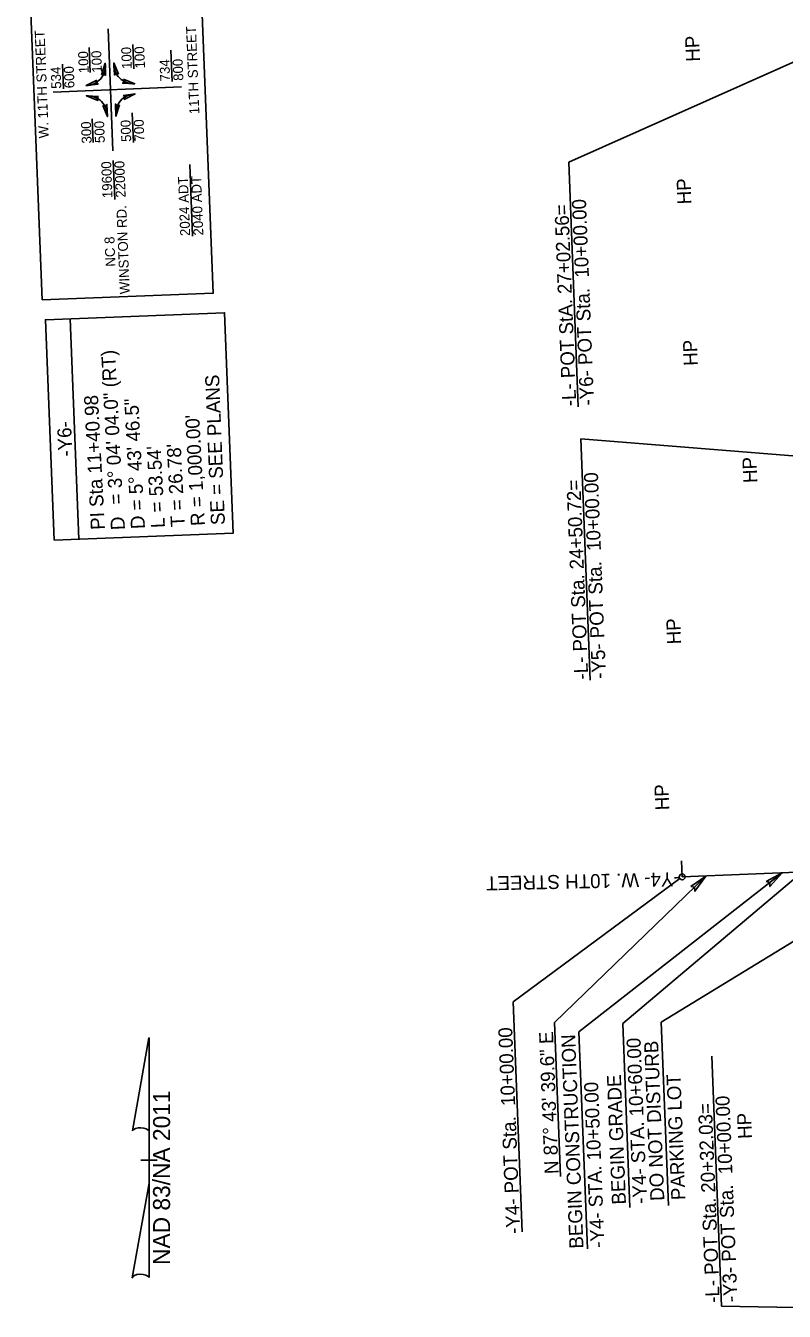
# Model space of a CAD drawing. Extents: x 1627861 to 1629601, y 761281 to 766239.
# Drawn here: x 1627959 to 1628338, y 762507 to 763149 of the extents above; entities that cross this region are included whole.
import ezdxf

# ---------------------------------------------------------------- set-up
doc = ezdxf.new("R2010")
doc.units = 0
for name, color, linetype in [('Cogo Default Point CELL', 7, 'Continuous'), ('Default', 7, 'Continuous'), ('Exist Other Culture Sign Leader', 7, 'Continuous'), ('Exist Right of Way Line Leader', 7, 'Continuous'), ('Exist Utilities Gas Meter CELL', 7, 'Continuous'), ('Exist Utilities Gas Meter Cogo Number', 7, 'Continuous'), ('Exist Utilities Gas UG Line Text', 7, 'Continuous'), ('Exist Utilities Power UG Cable SUE LOS B Cogo Number', 7, 'Continuous'), ('Exist Utilities Power UG Cable SUE LOS B Cogo Point CELL', 7, 'Continuous'), ('Exist Utilities Water Meter Cogo Elevation', 7, 'Continuous'), ('Exist Utilities Water UG Line SUE LOS B Cogo Point CELL', 7, 'Continuous'), ('Scratch_Level_0', 7, 'Continuous')]:
    doc.layers.add(name, color=color, linetype=linetype)

msp = doc.modelspace()

# ---------------------------------------------------------------- linework, layer by layer
at = {"layer": 'Default'}
for p, q in [((1628003.02, 763087.05), (1628000.62, 763147.93)), ((1628013.39, 763127.98), (1628012.91, 763140.11)), ((1627991.71, 763126.05), (1627991.22, 763138.65)), ((1628032.57, 763121.55), (1628031.95, 763137.34)), ((1627978.27, 763117.98), (1627977.78, 763130.29)), ((1627973.11, 763116.36), (1628037.27, 763118.89)), ((1627993.13, 763091.11), (1627992.67, 763103)), ((1628013.23, 763091.14), (1628012.64, 763106)), ((1628003.9, 763062.69), (1628003.13, 763082.11)), ((1628042.8, 763044.26), (1628041.39, 763080.08))]:
    msp.add_line(p, q, dxfattribs=at)
msp.add_lwpolyline([(1627967.61, 763012.46), (1627959.45, 763219.4), (1628045, 763222.77), (1628053.16, 763015.84)], close=True, dxfattribs=at)
for centre, start, end in [((1627989.39, 763129.45), 271.2141, 7.3945), ((1628013.3, 763130.4), 177.12188, 273.30228), ((1627990.37, 763104.59), 357.12188, 93.30228), ((1628014.28, 763105.53), 91.2141, 187.3945)]:
    msp.add_arc(centre, 9.89, start, end, dxfattribs=at)
at = {"layer": 'Exist Right of Way Line Leader'}
for p, q in [((1628442.93, 763175.97), (1628230.65, 763081.26)), ((1628235.47, 762959), (1628230.65, 763081.26)), ((1628452.26, 762925.69), (1628236.66, 762943.11)), ((1628241.42, 762822.52), (1628236.66, 762943.11)), ((1628286.14, 762723.35), (1628202.95, 762661.81)), ((1628223.6, 762651.48), (1628299.14, 762724.5)), ((1628207.48, 762546.9), (1628202.95, 762661.81)), ((1628226.64, 762574.51), (1628223.6, 762651.48)), ((1628307.04, 762509.67), (1628302.12, 762634.58)), ((1628468.75, 762507.18), (1628307.04, 762509.67))]:
    msp.add_line(p, q, dxfattribs=at)
msp.add_circle((1628287.35, 762724.24), 1.5, dxfattribs=at)
at = {"layer": 'Exist Utilities Gas Meter CELL'}
msp.add_line((1628287.35, 762724.24), (1628461.42, 762731.15), dxfattribs=at)
at = {"layer": 'Exist Utilities Gas Meter Cogo Number'}
for points in [[(1628291.59, 762719.36), (1628299.14, 762724.5), (1628293.74, 762717.06), (1628293.46, 762719.01)], [(1628329.26, 762721.9), (1628337.31, 762726.22), (1628331.16, 762719.39), (1628331.08, 762721.36)]]:
    msp.add_lwpolyline(points, close=True, dxfattribs=at)
at = {"layer": 'Exist Utilities Gas UG Line Text'}
msp.add_line((1627981.6, 763003.03), (1627985.94, 762892.93), dxfattribs=at)
msp.add_lwpolyline([(1627973.6, 762892.44), (1627969.26, 763002.54), (1628058.8, 763006.07), (1628063.14, 762895.97)], close=True, dxfattribs=at)
at = {"layer": 'Exist Utilities Power UG Cable SUE LOS B Cogo Number'}
for p, q in [((1628012.79, 762597.41), (1628021.01, 762643.76)), ((1628021.06, 762643.76), (1628021.01, 762643.76)), ((1628021.06, 762643.76), (1628021.01, 762643.76)), ((1628021.06, 762643.76), (1628021.04, 762595.96)), ((1628021.03, 762571.16), (1628021.04, 762597.36)), ((1628021.04, 762595.96), (1628021.04, 762597.31)), ((1628017.03, 762582.76), (1628016.98, 762582.76)), ((1628020.58, 762582.76), (1628017.03, 762582.76)), ((1628017.08, 762582.76), (1628025.08, 762582.76)), ((1628021.03, 762571.16), (1628012.66, 762523.91)), ((1628021.06, 762524.11), (1628021.03, 762571.16))]:
    msp.add_line(p, q, dxfattribs=at)
for centre, start_param, end_param in [((1628016.93, 762596.91), 0.216388, 2.908219), ((1628016.89, 762523.74), 0.201328, 3.141593)]:
    msp.add_ellipse(centre, major_axis=(4.23, -0.03), ratio=0.461098, start_param=start_param, end_param=end_param, dxfattribs=at)
at = {"layer": 'Exist Utilities Water Meter Cogo Elevation'}
msp.add_line((1628287.35, 762724.24), (1628287.03, 762732.23), dxfattribs=at)
at = {"layer": 'Exist Utilities Water UG Line SUE LOS B Cogo Point CELL'}
for points in [[(1627997.28, 763125.02), (1627999.2, 763130.73), (1627999.32, 763124.67), (1627998.4, 763125.58)], [(1628005.74, 763125.34), (1628003.42, 763130.89), (1628003.73, 763124.84), (1628004.58, 763125.82)], [(1627994.95, 763122.33), (1627989.6, 763119.56), (1627995.61, 763120.36), (1627994.57, 763121.14)], [(1628008.29, 763122.78), (1628013.87, 763120.52), (1628007.81, 763120.76), (1628008.78, 763121.63)], [(1627995.82, 763114.15), (1627989.8, 763114.46), (1627995.39, 763112.12), (1627994.88, 763113.31)], [(1628008.1, 763114.67), (1628014.07, 763115.42), (1628008.67, 763112.68), (1628009.09, 763113.91)], [(1627997.95, 763109.65), (1628000.25, 763104.09), (1627999.97, 763110.14), (1627999.11, 763109.17)], [(1628006.33, 763109.98), (1628004.47, 763104.26), (1628004.28, 763110.31), (1628005.22, 763109.41)]]:
    msp.add_lwpolyline(points, close=True, dxfattribs=at)
at = {"layer": 'Scratch_Level_0'}
for p, q in [((1628337.31, 762726.22), (1628235.71, 762646.83)), ((1628347.3, 762726.62), (1628257.63, 762650.98)), ((1628358.46, 762701.49), (1628276.84, 762651.68)), ((1628276.84, 762651.68), (1628280.45, 762560.11)), ((1628235.71, 762646.83), (1628239.98, 762538.42)), ((1628257.63, 762650.98), (1628261.25, 762559))]:
    msp.add_line(p, q, dxfattribs=at)

# ---------------------------------------------------------------- texts
at = {"layer": 'Cogo Default Point CELL'}
msp.add_text('N 87%%d 43\' 39.6" E', height=7, rotation=92.25819, dxfattribs=at).set_placement((1628225.63, 762575.87))
at = {"layer": 'Default'}
for s, height, p in [('W. 11TH STREET', 4.9438, (1627970.99, 763093.34)), ('11TH STREET', 4.9438, (1628046.19, 763105.33)), ('100', 4.944, (1627990.96, 763125.86)), ('100', 4.944, (1627997.55, 763126.12)), ('100', 4.944, (1628012.48, 763127.96)), ('100', 4.944, (1628019.06, 763128.22)), ('534', 4.944, (1627977.25, 763118.08)), ('600', 4.944, (1627983.84, 763118.34)), ('734', 4.944, (1628031.63, 763121.78)), ('800', 4.944, (1628038.22, 763122.04)), ('300', 4.944, (1627992.41, 763090.72)), ('500', 4.944, (1627999, 763090.98)), ('500', 4.944, (1628012.17, 763091.51)), ('700', 4.944, (1628018.76, 763091.77)), ('19600', 4.944, (1628002.8, 763063.44)), ('22000', 4.944, (1628009.39, 763063.7)), ('2024 ADT', 4.944, (1628041.6, 763044.52)), ('2040 ADT', 4.944, (1628048.19, 763044.78)), ('WINSTON RD.', 4.9438, (1628011.42, 763015.48)), ('NC 8', 4.944, (1628004.29, 763029.18))]:
    msp.add_text(s, height=height, rotation=92.25819, dxfattribs=at).set_placement(p)
at = {"layer": 'Exist Other Culture Sign Leader'}
for s, rotation, p in [('HP', 92.25819, (1628296.29, 763131.65)), ('HP', 92.25819, (1628292.02, 763060.38)), ('HP', 92.25819, (1628295.2, 762979.7)), ('HP', 92.25819, (1628324.89, 762921.15)), ('HP', 92.25819, (1628286.87, 762840.55)), ('HP', 92.25819, (1628280.96, 762757.64)), ('-Y4- W. 10TH STREET', 181.25238, (1628286.01, 762726.55)), ('BEGIN CONSTRUCTION', 92.25819, (1628238.07, 762538.62)), ('-Y4- STA. 10+60.00', 92.25819, (1628269.78, 762561.04)), ('-Y4- STA. 10+50.00', 92.25819, (1628248.56, 762539.03)), ('BEGIN GRADE', 92.25819, (1628259.28, 762560.63)), ('HP', 92.25819, (1628322.21, 762593.45))]:
    msp.add_text(s, height=7, rotation=rotation, dxfattribs=at).set_placement(p)
at = {"layer": 'Exist Right of Way Line Leader'}
for s, p in [('-L- POT StA. 27+02.56=', (1628234.46, 762959.48)), ('-Y6- POT Sta.  10+00.00', (1628243.32, 762959.83)), ('-L- POT Sta. 24+50.72=', (1628240.43, 762822.95)), ('-Y5- POT Sta.  10+00.00', (1628249.3, 762823.3)), ('-Y4- POT Sta.  10+00.00', (1628206.49, 762545.99)), ('-Y3- POT Sta.  10+00.00', (1628314.99, 762511.84)), ('-L- POT Sta. 20+32.03=', (1628306.12, 762511.49))]:
    msp.add_text(s, height=7, rotation=92.25819, dxfattribs=at).set_placement(p)
at = {"layer": 'Exist Utilities Gas UG Line Text'}
for s, rotation, p in [('= 3%%d 04\' 04.0" (RT)', 92.97913, (1628008.08, 762910.49)), ('SE = SEE PLANS', 92.25804, (1628058.98, 762900.14)), ('PI Sta 11+40.98', 92.97913, (1627999.02, 762897.82)), ('D = 5%%d 43\' 46.5"', 92.97913, (1628019.03, 762898.19)), ("R = 1,000.00'", 92.97913, (1628048.99, 762899.75)), ('-Y6-', 92.25819, (1627982.76, 762934.33)), ("L = 53.54'", 92.97913, (1628029.01, 762898.71)), ("T = 26.78'", 92.97913, (1628039, 762899.23)), ('D', 92.97913, (1628009.04, 762897.67))]:
    msp.add_text(s, height=7, rotation=rotation, dxfattribs=at).set_placement(p)
at = {"layer": 'Exist Utilities Power UG Cable SUE LOS B Cogo Number'}
msp.add_text('NAD 83/NA 2011', height=8.5, rotation=89.97566, dxfattribs=at).set_placement((1628031.53, 762530.33))
at = {"layer": 'Exist Utilities Power UG Cable SUE LOS B Cogo Point CELL'}
for s, p in [('DO NOT DISTURB ', (1628278.45, 762562.47)), ('PARKING LOT', (1628288.94, 762562.89))]:
    msp.add_text(s, height=7, rotation=92.25819, dxfattribs=at).set_placement(p)

doc.saveas('drawing.dxf')
